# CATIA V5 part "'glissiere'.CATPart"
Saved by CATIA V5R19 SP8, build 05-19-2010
Part number: 'glissière'
Bounding box of the stored display mesh (mm): x -39.5 to -13.5, y -37 to 37, z -16.5 to 16.5
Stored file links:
  C:\Users\ThinkMotion\Desktop\EU_thinkMotion\iao\IAO_MMS_Groupe3\ecartoux\projet_IAO_ecartoux\projet_IAO_ecartoux\griffe_d'une_camera_ecartoux\'glissiere'.CATPart
  C:\Users\ThinkMotion\Desktop\EU_thinkMotion\iao\IAO_MMS_Groupe3\ecartoux\projet_IAO_ecartoux\projet_IAO_ecartoux\griffe_d'une_camera_ecartoux\Mecanisme_a_coulisse_et_leviers_de_la_griffe_d'un_camera_ecartoux.CATProduct
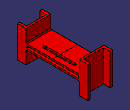
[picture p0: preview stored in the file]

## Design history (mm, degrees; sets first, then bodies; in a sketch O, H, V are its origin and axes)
Set1
  Plane1: linked copy from another document
  Line1: linked copy from another document
  Point1 to Point3: linked copy from another document
  Plane2: linked copy from another document
  Line2: linked copy from another document
  Point4 to Point6: linked copy from another document
Body1 (main body)
  Sketch1 on Plane1, origin (0, 0, 0), H (0, 1, 0), V (0, 0, 1)
    point P1 (-38, 16.5)
    line L1 (-38, 16.5) -> (-28, 16.5)
    line L2 (-28, 16.5) -> (-28, 3)
    line L3 (-28, -16.5) -> (-38, -16.5)
    line L4 (-38, -16.5) -> (-38, 16.5)
    point P2 (-28, 16.5)
    point P3 (-28, -16.5)
    point P4 (-38, -16.5)
    reference projected line E1 (-30, -16.5) -> (-30, 16.5) from Line1
    reference projected point E2 (0, 0) from Point1
    axis line L5 (0, 25.9867) -> (0, -20.0134)
    point P5 (0, 25.9867)
    line L6 (-28, -3) -> (0, -3)
    point P7 (-28, -3)
    point P8 (0, -3)
    point P9 (0, 3)
    point P10 (-28, 3)
    line L7 (-28, 3) -> (0, 3)
    reference projected point E3 (0, 0) from Point1
    line L8 (-28, -3) -> (-28, -16.5)
    point P11 (0, 0)
    construction line L9 through (0, 0) direction (0, 1)
    point P14 (38, 16.5)
    point P15 (28, 16.5)
    point P16 (28, -16.5)
    point P17 (38, -16.5)
    point P18 (28, -3)
    point P19 (0, -3)
    point P20 (0, 3)
    point P21 (28, 3)
    line L10 (38, 16.5) -> (28, 16.5)
    line L11 (28, 16.5) -> (28, 3)
    line L12 (28, -16.5) -> (38, -16.5)
    line L13 (38, -16.5) -> (38, 16.5)
    line L14 (28, -3) -> (0, -3)
    line L15 (28, 3) -> (0, 3)
    line L16 (28, -3) -> (28, -16.5)
    distance L2 E1 = 2
    distance L4 L2 = 10
    distance L1 L3 = 33
    distance L1 E2 = 16.5
    distance L7 L6 = 6
    distance E3 L7 = 3
    horizontal: L1 H, L3 H, L6 H, L7 H
    vertical: L2 V, L4 V, L5 V, L8 V
    coincidence: P5 V, P7 L2, P9 L5, P8 L5, L2 L8, P8 P19, P9 P20
    symmetry: O P11 L5, V L9 L5, P1 P14 L5, P2 P15 L5, P3 P16 L5, P4 P17 L5, P7 P18 L5, P8 P19 L5, P9 P20 L5, P10 P21 L5, L1 L10 L5, L2 L11 L5, L3 L12 L5, L4 L13 L5, L6 L14 L5, L7 L15 L5, L8 L16 L5
  Sketch2 on Plane2, origin (0, 0, 0), H (1, 0, 0), V (0, 1, 0)
    point P1 (-16, 37)
    line L1 (-37, 37) -> (-37, 30)
    line L2 (-37, 30) -> (-16, 30)
    line L3 (-16, 30) -> (-16, 37)
    point P2 (-37, 37)
    point P3 (-37, 30)
    point P4 (-16, 30)
    point P5 (-13.5, 37)
    line L4 (-13.5, 37) -> (-16, 37)
    line L5 (-39.5, 37) -> (-39.5, 0)
    line L6 (-13.5, 0) -> (-13.5, 37)
    point P6 (-39.5, 37)
    point P7 (-39.5, 0)
    point P8 (-13.5, 0)
    line L7 (-37, 37) -> (-39.5, 37)
    reference projected point E1 (-16, 30) from Point4
    reference projected point E2 (-37, 30) from Point5
    axis line L8 (-59.0675, 0) -> (19.0254, 0)
    point P9 (-59.0675, 0)
    point P11 (-39.5, 0)
    point P12 (-39.5, -37)
    line L9 (-39.5, -37) -> (-39.5, 0)
    point P13 (-37, -37)
    line L10 (-37, -37) -> (-39.5, -37)
    point P14 (-37, -30)
    line L11 (-37, -37) -> (-37, -30)
    point P15 (-16, -30)
    line L12 (-37, -30) -> (-16, -30)
    point P16 (-16, -37)
    line L13 (-16, -30) -> (-16, -37)
    point P17 (-13.5, -37)
    line L14 (-13.5, -37) -> (-16, -37)
    point P18 (-13.5, 0)
    line L15 (-13.5, 0) -> (-13.5, -37)
    length L7 = 2.5
    length L4 = 2.5
    length L1 = 7
    horizontal: L2 H, L4 H, L7 H, L8 H
    vertical: L1 V, L3 V, L5 V, L6 V
    coincidence: L4 L7, P4 E1, P3 E2, P9 H, P7 L8, P8 L8, P7 P11, P8 P18
    symmetry: P7 P11 L8, P6 P12 L8, L5 L9 L8, P2 P13 L8, L7 L10 L8, P3 P14 L8, L1 L11 L8, P4 P15 L8, L2 L12 L8, P1 P16 L8, L3 L13 L8, P5 P17 L8, L4 L14 L8, P8 P18 L8, L6 L15 L8
  SolidCombine1: FirstComponentProfile Sketch1, FirstComponentDirection Sketch1, SecondComponentProfile Sketch2, SecondComponentDirection Sketch2
  Sketch3 on Plane1, origin (0, 0, 0), H (0, 1, 0), V (0, 0, 1)
    point P1 (-27, 1.25)
    line L1 (-27, 1.25) -> (27, 1.25)
    line L2 (27, 1.25) -> (27, -1.25)
    line L3 (27, -1.25) -> (-27, -1.25)
    line L4 (-27, -1.25) -> (-27, 1.25)
    point P3 (27, -1.25)
    point P4 (-27, -1.25)
    reference projected point E1 (-27, 1.25) from Point2
    reference projected point E2 (-27, -1.25) from Point3
    reference projected point E3 (27, -1.25) from Point6
    horizontal: L1 H, L3 H
    vertical: L2 V, L4 V
    coincidence: E1 P1, P4 E2, P3 E3
  Pocket1: profile Sketch3, direction (-1, 0, 0), length 40
  Fillet1: radius 1, on edge [face of SolidCombine1 from Sketch1.L2 | face of SolidCombine1 from Sketch1.L7]; edge [face of SolidCombine1 from Sketch1.L15 | face of SolidCombine1 from Sketch1.L11]; edge [face of SolidCombine1 from Sketch1.L6 | face of SolidCombine1 from Sketch1.L8]; edge [face of SolidCombine1 from Sketch1.L16 | face of SolidCombine1 from Sketch1.L14]
  Sketch4 on Plane2, origin (0, 0, 0), H (1, 0, 0), V (0, 1, 0)
    line L1 (-21.5, 16.6132) -> (-21.5, -14.8868)
    line L2 (-18.5, -14.8868) -> (-18.5, 16.6132)
    point P3 (-21.5, -14.8868)
    point P4 (-18.5, -14.8868)
    reference projected point E1 (0, 0) from Point1
    arc A1 centre (-20, 16.6132) radius 1.5 from (-18.5, 16.6132) to (-21.5, 16.6132) ccw
    point P5 (-20, 16.6132)
    point P6 (-20, -14.8868)
    arc A2 centre (-20, -14.8868) radius 1.5 from (-21.5, -14.8868) to (-18.5, -14.8868) ccw
    point P7 (-21.5, -14.8868)
    point P8 (-18.5, -14.8868)
    reference projected point E2 (0, 0) from Point1
    distance L1 L2 = 3
    distance E1 L2 = 18.5
    radius A1 = 1.5
    radius A2 = 1.5
    distance P5 E2 = 26
    distance P5 P6 = 31.5
    vertical: L1 V, L2 V
    coincidence: A2 P3, L2 P8, L1 P7, P3 P7, P4 P8
    tangency: A2 L2, A1 L2
  Pocket2: profile Sketch4, direction (0, 0, -1), length 5, mirrored extent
